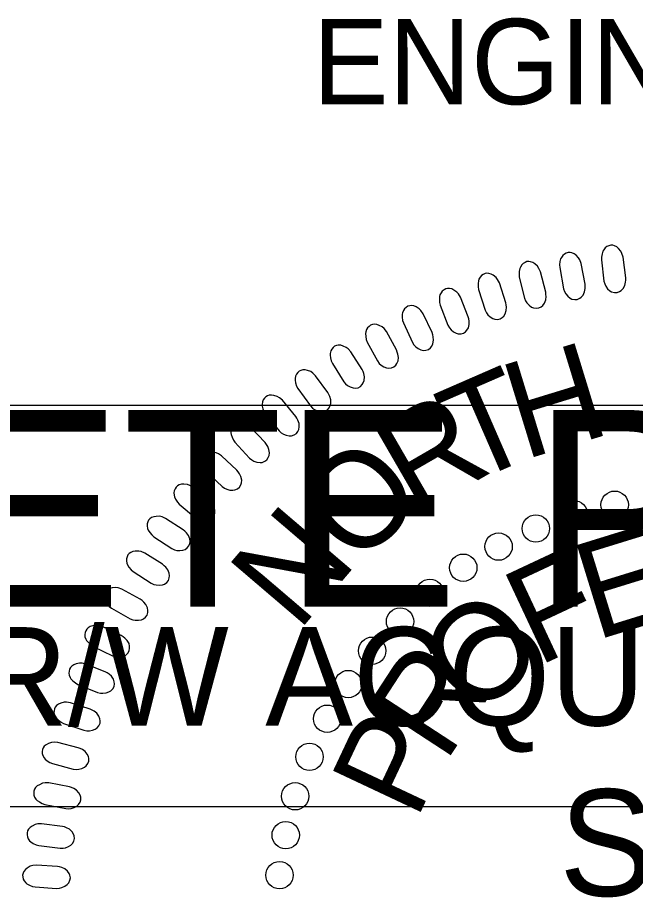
# Model space of a CAD drawing. Extents: x 505602 to 507286, y 483109 to 484209.
# Drawn here: x 507178.9 to 507215, y 484097.2 to 484148.7 of the extents above; entities that cross this region are included whole.
import ezdxf

# ---------------------------------------------------------------- set-up
doc = ezdxf.new("R2010")
doc.units = 0
for name, color, linetype in [('Sheet PE Seal Cell', 7, 'Continuous'), ('Sheet Profile CELL', 7, 'Continuous'), ('Sheet Sticker Incomplete CELL', 7, 'Continuous')]:
    doc.layers.add(name, color=color, linetype=linetype)

msp = doc.modelspace()

# ---------------------------------------------------------------- linework, layer by layer
at = {"layer": 'Sheet PE Seal Cell'}
for points in [[(507214.482, 484133.465), (507214.328, 484134.682), (507214.264, 484134.896), (507214.194, 484135.027), (507214.062, 484135.182), (507213.952, 484135.278), (507213.831, 484135.343), (507213.722, 484135.37), (507213.608, 484135.376), (507213.499, 484135.342), (507213.384, 484135.297), (507213.288, 484135.225), (507213.196, 484135.113), (507213.147, 484135.026), (507213.099, 484134.869), (507213.062, 484134.684), (507213.06, 484134.523), (507213.21, 484133.275), (507213.253, 484133.11), (507213.315, 484132.977), (507213.424, 484132.829), (507213.553, 484132.705), (507213.659, 484132.638), (507213.822, 484132.598), (507213.973, 484132.597), (507214.116, 484132.655), (507214.214, 484132.718), (507214.328, 484132.833), (507214.425, 484133.016), (507214.469, 484133.202), (507214.483, 484133.335)], [(507212.1, 484133.097), (507211.871, 484134.302), (507211.793, 484134.511), (507211.716, 484134.638), (507211.574, 484134.784), (507211.458, 484134.873), (507211.333, 484134.931), (507211.223, 484134.95), (507211.109, 484134.949), (507211.002, 484134.909), (507210.891, 484134.857), (507210.799, 484134.779), (507210.714, 484134.66), (507210.671, 484134.571), (507210.633, 484134.411), (507210.608, 484134.224), (507210.615, 484134.063), (507210.843, 484132.828), (507210.897, 484132.665), (507210.967, 484132.536), (507211.085, 484132.396), (507211.221, 484132.28), (507211.332, 484132.22), (507211.497, 484132.19), (507211.647, 484132.199), (507211.787, 484132.266), (507211.881, 484132.335), (507211.987, 484132.456), (507212.073, 484132.645), (507212.105, 484132.834), (507212.11, 484132.967)], [(507209.795, 484132.625), (507209.491, 484133.813), (507209.4, 484134.016), (507209.314, 484134.139), (507209.164, 484134.275), (507209.042, 484134.357), (507208.914, 484134.407), (507208.802, 484134.42), (507208.689, 484134.411), (507208.585, 484134.364), (507208.477, 484134.305), (507208.39, 484134.221), (507208.314, 484134.098), (507208.276, 484134.007), (507208.247, 484133.845), (507208.234, 484133.656), (507208.252, 484133.496), (507208.557, 484132.277), (507208.621, 484132.118), (507208.699, 484131.994), (507208.826, 484131.862), (507208.969, 484131.754), (507209.083, 484131.702), (507209.25, 484131.682), (507209.4, 484131.7), (507209.535, 484131.776), (507209.624, 484131.85), (507209.722, 484131.978), (507209.795, 484132.172), (507209.816, 484132.363), (507209.813, 484132.495)], [(507207.461, 484132.004), (507207.083, 484133.171), (507206.98, 484133.368), (507206.887, 484133.485), (507206.728, 484133.612), (507206.602, 484133.686), (507206.47, 484133.727), (507206.358, 484133.733), (507206.246, 484133.717), (507206.145, 484133.664), (507206.041, 484133.598), (507205.96, 484133.51), (507205.891, 484133.382), (507205.859, 484133.288), (507205.84, 484133.125), (507205.839, 484132.935), (507205.867, 484132.776), (507206.248, 484131.579), (507206.322, 484131.425), (507206.407, 484131.306), (507206.542, 484131.182), (507206.692, 484131.084), (507206.809, 484131.038), (507206.977, 484131.029), (507207.125, 484131.057), (507207.255, 484131.141), (507207.339, 484131.221), (507207.429, 484131.354), (507207.49, 484131.553), (507207.499, 484131.744), (507207.487, 484131.877)], [(507205.261, 484131.188), (507204.809, 484132.329), (507204.694, 484132.519), (507204.594, 484132.63), (507204.427, 484132.746), (507204.297, 484132.813), (507204.163, 484132.845), (507204.051, 484132.844), (507203.94, 484132.821), (507203.843, 484132.761), (507203.742, 484132.689), (507203.667, 484132.595), (507203.606, 484132.464), (507203.58, 484132.368), (507203.572, 484132.204), (507203.583, 484132.015), (507203.621, 484131.859), (507204.076, 484130.687), (507204.159, 484130.538), (507204.253, 484130.425), (507204.395, 484130.309), (507204.55, 484130.221), (507204.67, 484130.182), (507204.838, 484130.184), (507204.984, 484130.221), (507205.108, 484130.313), (507205.187, 484130.398), (507205.269, 484130.537), (507205.318, 484130.739), (507205.314, 484130.931), (507205.295, 484131.062)], [(507203.143, 484130.255), (507202.621, 484131.365), (507202.494, 484131.548), (507202.387, 484131.652), (507202.214, 484131.759), (507202.079, 484131.816), (507201.944, 484131.84), (507201.832, 484131.832), (507201.722, 484131.802), (507201.629, 484131.736), (507201.534, 484131.659), (507201.464, 484131.56), (507201.412, 484131.425), (507201.392, 484131.328), (507201.395, 484131.163), (507201.417, 484130.975), (507201.464, 484130.822), (507201.993, 484129.682), (507202.085, 484129.537), (507202.185, 484129.43), (507202.334, 484129.324), (507202.495, 484129.245), (507202.617, 484129.215), (507202.784, 484129.227), (507202.928, 484129.272), (507203.046, 484129.372), (507203.12, 484129.462), (507203.192, 484129.606), (507203.229, 484129.81), (507203.213, 484130.002), (507203.185, 484130.132)], [(507201.06, 484129.241), (507200.469, 484130.317), (507200.331, 484130.491), (507200.218, 484130.588), (507200.038, 484130.683), (507199.9, 484130.732), (507199.764, 484130.748), (507199.653, 484130.733), (507199.545, 484130.696), (507199.456, 484130.625), (507199.366, 484130.541), (507199.303, 484130.438), (507199.259, 484130.3), (507199.245, 484130.201), (507199.258, 484130.038), (507199.292, 484129.851), (507199.349, 484129.701), (507199.948, 484128.596), (507200.049, 484128.458), (507200.156, 484128.358), (507200.311, 484128.261), (507200.477, 484128.192), (507200.6, 484128.169), (507200.767, 484128.192), (507200.907, 484128.247), (507201.019, 484128.354), (507201.087, 484128.448), (507201.15, 484128.597), (507201.173, 484128.803), (507201.146, 484128.993), (507201.109, 484129.12)], [(507199.043, 484128.099), (507198.386, 484129.135), (507198.237, 484129.301), (507198.118, 484129.39), (507197.933, 484129.474), (507197.792, 484129.514), (507197.655, 484129.522), (507197.544, 484129.499), (507197.439, 484129.456), (507197.355, 484129.379), (507197.27, 484129.29), (507197.214, 484129.184), (507197.179, 484129.043), (507197.171, 484128.944), (507197.194, 484128.781), (507197.24, 484128.598), (507197.306, 484128.45), (507197.973, 484127.385), (507198.083, 484127.254), (507198.196, 484127.16), (507198.357, 484127.074), (507198.526, 484127.016), (507198.651, 484127), (507198.816, 484127.034), (507198.952, 484127.097), (507199.058, 484127.211), (507199.119, 484127.309), (507199.173, 484127.461), (507199.183, 484127.669), (507199.144, 484127.857), (507199.1, 484127.982)], [(507197.042, 484126.745), (507196.321, 484127.737), (507196.162, 484127.893), (507196.038, 484127.976), (507195.847, 484128.047), (507195.704, 484128.078), (507195.567, 484128.077), (507195.458, 484128.048), (507195.356, 484127.998), (507195.277, 484127.916), (507195.198, 484127.822), (507195.149, 484127.712), (507195.122, 484127.569), (507195.121, 484127.47), (507195.155, 484127.309), (507195.211, 484127.129), (507195.287, 484126.987), (507196.019, 484125.965), (507196.137, 484125.841), (507196.255, 484125.754), (507196.421, 484125.678), (507196.594, 484125.631), (507196.72, 484125.623), (507196.882, 484125.667), (507197.015, 484125.739), (507197.112, 484125.859), (507197.167, 484125.961), (507197.212, 484126.116), (507197.209, 484126.324), (507197.158, 484126.509), (507197.106, 484126.631)], [(507195.162, 484125.356), (507194.38, 484126.301), (507194.212, 484126.446), (507194.082, 484126.521), (507193.888, 484126.58), (507193.743, 484126.603), (507193.606, 484126.593), (507193.5, 484126.556), (507193.401, 484126.5), (507193.327, 484126.413), (507193.254, 484126.314), (507193.211, 484126.202), (507193.194, 484126.058), (507193.199, 484125.958), (507193.242, 484125.8), (507193.31, 484125.624), (507193.395, 484125.486), (507194.189, 484124.513), (507194.315, 484124.397), (507194.439, 484124.318), (507194.609, 484124.252), (507194.785, 484124.216), (507194.911, 484124.216), (507195.07, 484124.27), (507195.198, 484124.35), (507195.287, 484124.476), (507195.336, 484124.581), (507195.371, 484124.739), (507195.354, 484124.946), (507195.292, 484125.127), (507195.232, 484125.246)], [(507193.374, 484123.817), (507192.535, 484124.711), (507192.357, 484124.846), (507192.223, 484124.912), (507192.025, 484124.959), (507191.88, 484124.972), (507191.744, 484124.954), (507191.64, 484124.911), (507191.544, 484124.849), (507191.476, 484124.758), (507191.409, 484124.654), (507191.374, 484124.539), (507191.366, 484124.394), (507191.377, 484124.295), (507191.43, 484124.14), (507191.51, 484123.968), (507191.602, 484123.837), (507192.457, 484122.915), (507192.589, 484122.807), (507192.717, 484122.736), (507192.892, 484122.681), (507193.07, 484122.656), (507193.195, 484122.663), (507193.35, 484122.728), (507193.473, 484122.816), (507193.554, 484122.947), (507193.597, 484123.055), (507193.622, 484123.215), (507193.593, 484123.42), (507193.518, 484123.597), (507193.452, 484123.712)], [(507191.712, 484122.207), (507190.818, 484123.047), (507190.632, 484123.17), (507190.495, 484123.228), (507190.294, 484123.262), (507190.148, 484123.267), (507190.013, 484123.24), (507189.912, 484123.191), (507189.821, 484123.123), (507189.759, 484123.028), (507189.699, 484122.919), (507189.67, 484122.803), (507189.671, 484122.658), (507189.689, 484122.56), (507189.751, 484122.408), (507189.841, 484122.242), (507189.942, 484122.115), (507190.853, 484121.25), (507190.992, 484121.15), (507191.124, 484121.087), (507191.302, 484121.043), (507191.48, 484121.03), (507191.605, 484121.045), (507191.757, 484121.119), (507191.873, 484121.214), (507191.946, 484121.351), (507191.982, 484121.461), (507191.996, 484121.622), (507191.955, 484121.825), (507191.87, 484121.997), (507191.796, 484122.107)], [(507190.098, 484120.421), (507189.154, 484121.203), (507188.96, 484121.314), (507188.82, 484121.363), (507188.617, 484121.385), (507188.471, 484121.38), (507188.339, 484121.344), (507188.241, 484121.289), (507188.154, 484121.215), (507188.098, 484121.116), (507188.045, 484121.005), (507188.024, 484120.886), (507188.034, 484120.742), (507188.057, 484120.645), (507188.13, 484120.498), (507188.23, 484120.337), (507188.338, 484120.218), (507189.301, 484119.411), (507189.446, 484119.32), (507189.583, 484119.266), (507189.763, 484119.233), (507189.941, 484119.231), (507190.065, 484119.255), (507190.211, 484119.337), (507190.322, 484119.439), (507190.387, 484119.58), (507190.415, 484119.693), (507190.419, 484119.854), (507190.365, 484120.054), (507190.27, 484120.221), (507190.188, 484120.326)], [(507188.574, 484118.718), (507187.544, 484119.384), (507187.339, 484119.472), (507187.193, 484119.504), (507186.99, 484119.502), (507186.845, 484119.479), (507186.718, 484119.428), (507186.628, 484119.362), (507186.55, 484119.279), (507186.505, 484119.174), (507186.466, 484119.057), (507186.459, 484118.937), (507186.486, 484118.795), (507186.52, 484118.701), (507186.61, 484118.564), (507186.728, 484118.415), (507186.85, 484118.31), (507187.901, 484117.622), (507188.056, 484117.549), (507188.197, 484117.511), (507188.38, 484117.5), (507188.558, 484117.518), (507188.678, 484117.557), (507188.813, 484117.656), (507188.911, 484117.77), (507188.959, 484117.918), (507188.974, 484118.033), (507188.959, 484118.194), (507188.882, 484118.386), (507188.767, 484118.54), (507188.674, 484118.635)], [(507187.359, 484116.696), (507186.324, 484117.353), (507186.119, 484117.439), (507185.973, 484117.47), (507185.769, 484117.467), (507185.625, 484117.443), (507185.497, 484117.391), (507185.408, 484117.324), (507185.33, 484117.24), (507185.287, 484117.134), (507185.249, 484117.018), (507185.243, 484116.897), (507185.271, 484116.756), (507185.306, 484116.662), (507185.397, 484116.525), (507185.516, 484116.378), (507185.639, 484116.274), (507186.696, 484115.594), (507186.851, 484115.522), (507186.993, 484115.485), (507187.175, 484115.475), (507187.353, 484115.495), (507187.473, 484115.534), (507187.607, 484115.635), (507187.704, 484115.751), (507187.751, 484115.898), (507187.765, 484116.013), (507187.749, 484116.174), (507187.67, 484116.365), (507187.554, 484116.519), (507187.461, 484116.614)], [(507186.056, 484114.646), (507184.981, 484115.238), (507184.771, 484115.311), (507184.623, 484115.332), (507184.421, 484115.316), (507184.277, 484115.283), (507184.154, 484115.224), (507184.069, 484115.151), (507183.997, 484115.063), (507183.961, 484114.955), (507183.929, 484114.836), (507183.931, 484114.715), (507183.968, 484114.576), (507184.009, 484114.485), (507184.107, 484114.353), (507184.236, 484114.215), (507184.365, 484114.118), (507185.462, 484113.506), (507185.621, 484113.443), (507185.765, 484113.416), (507185.949, 484113.417), (507186.125, 484113.448), (507186.242, 484113.495), (507186.37, 484113.603), (507186.459, 484113.725), (507186.496, 484113.875), (507186.503, 484113.99), (507186.477, 484114.15), (507186.386, 484114.336), (507186.262, 484114.482), (507186.162, 484114.571)], [(507184.947, 484112.522), (507183.837, 484113.045), (507183.623, 484113.105), (507183.474, 484113.117), (507183.273, 484113.088), (507183.132, 484113.047), (507183.013, 484112.979), (507182.932, 484112.901), (507182.866, 484112.808), (507182.836, 484112.699), (507182.813, 484112.577), (507182.822, 484112.458), (507182.868, 484112.321), (507182.914, 484112.233), (507183.021, 484112.108), (507183.158, 484111.977), (507183.292, 484111.888), (507184.427, 484111.346), (507184.589, 484111.295), (507184.735, 484111.276), (507184.917, 484111.289), (507185.091, 484111.331), (507185.205, 484111.385), (507185.326, 484111.501), (507185.408, 484111.628), (507185.435, 484111.78), (507185.435, 484111.897), (507185.399, 484112.054), (507185.297, 484112.234), (507185.163, 484112.371), (507185.058, 484112.454)], [(507184.008, 484110.404), (507182.868, 484110.855), (507182.65, 484110.901), (507182.501, 484110.905), (507182.302, 484110.863), (507182.164, 484110.813), (507182.049, 484110.738), (507181.973, 484110.655), (507181.913, 484110.558), (507181.89, 484110.447), (507181.874, 484110.324), (507181.891, 484110.205), (507181.945, 484110.072), (507181.997, 484109.986), (507182.112, 484109.868), (507182.257, 484109.747), (507182.396, 484109.667), (507183.562, 484109.197), (507183.727, 484109.156), (507183.874, 484109.146), (507184.055, 484109.17), (507184.226, 484109.223), (507184.337, 484109.284), (507184.451, 484109.408), (507184.524, 484109.539), (507184.542, 484109.693), (507184.534, 484109.809), (507184.488, 484109.964), (507184.374, 484110.137), (507184.232, 484110.266), (507184.122, 484110.342)], [(507183.132, 484108.215), (507181.965, 484108.594), (507181.745, 484108.626), (507181.596, 484108.62), (507181.4, 484108.566), (507181.265, 484108.507), (507181.155, 484108.425), (507181.085, 484108.338), (507181.032, 484108.237), (507181.016, 484108.125), (507181.007, 484108.002), (507181.032, 484107.884), (507181.094, 484107.753), (507181.152, 484107.672), (507181.273, 484107.561), (507181.425, 484107.449), (507181.57, 484107.378), (507182.763, 484106.982), (507182.931, 484106.951), (507183.078, 484106.951), (507183.257, 484106.987), (507183.424, 484107.051), (507183.531, 484107.118), (507183.636, 484107.248), (507183.701, 484107.385), (507183.709, 484107.539), (507183.694, 484107.654), (507183.639, 484107.806), (507183.515, 484107.972), (507183.364, 484108.092), (507183.25, 484108.16)], [(507182.428, 484105.959), (507181.239, 484106.264), (507181.018, 484106.282), (507180.869, 484106.267), (507180.677, 484106.201), (507180.547, 484106.134), (507180.441, 484106.045), (507180.377, 484105.953), (507180.329, 484105.85), (507180.321, 484105.737), (507180.32, 484105.613), (507180.352, 484105.496), (507180.423, 484105.371), (507180.485, 484105.293), (507180.613, 484105.19), (507180.772, 484105.088), (507180.921, 484105.026), (507182.136, 484104.706), (507182.306, 484104.686), (507182.452, 484104.694), (507182.629, 484104.742), (507182.792, 484104.815), (507182.894, 484104.89), (507182.991, 484105.027), (507183.047, 484105.167), (507183.046, 484105.321), (507183.024, 484105.435), (507182.959, 484105.583), (507182.825, 484105.741), (507182.667, 484105.851), (507182.549, 484105.912)], [(507181.916, 484103.663), (507180.712, 484103.893), (507180.489, 484103.898), (507180.342, 484103.873), (507180.154, 484103.794), (507180.028, 484103.72), (507179.929, 484103.624), (507179.87, 484103.529), (507179.829, 484103.423), (507179.828, 484103.309), (507179.835, 484103.186), (507179.874, 484103.072), (507179.952, 484102.951), (507180.019, 484102.877), (507180.154, 484102.782), (507180.319, 484102.69), (507180.471, 484102.638), (507181.705, 484102.394), (507181.875, 484102.385), (507182.021, 484102.403), (507182.194, 484102.461), (507182.352, 484102.545), (507182.449, 484102.626), (507182.537, 484102.768), (507182.585, 484102.912), (507182.574, 484103.066), (507182.544, 484103.178), (507182.47, 484103.322), (507182.327, 484103.471), (507182.162, 484103.571), (507182.041, 484103.624)], [(507181.496, 484101.349), (507180.279, 484101.503), (507180.057, 484101.494), (507179.911, 484101.46), (507179.729, 484101.369), (507179.608, 484101.287), (507179.515, 484101.186), (507179.462, 484101.087), (507179.428, 484100.978), (507179.434, 484100.864), (507179.449, 484100.742), (507179.495, 484100.631), (507179.581, 484100.514), (507179.653, 484100.445), (507179.792, 484100.359), (507179.963, 484100.277), (507180.118, 484100.235), (507181.364, 484100.07), (507181.535, 484100.071), (507181.679, 484100.098), (507181.848, 484100.166), (507182.001, 484100.26), (507182.093, 484100.347), (507182.172, 484100.495), (507182.211, 484100.641), (507182.189, 484100.794), (507182.153, 484100.904), (507182.07, 484101.043), (507181.917, 484101.183), (507181.747, 484101.272), (507181.623, 484101.318)], [(507181.21, 484099.005), (507179.985, 484099.082), (507179.764, 484099.059), (507179.621, 484099.016), (507179.445, 484098.915), (507179.329, 484098.824), (507179.242, 484098.718), (507179.196, 484098.616), (507179.169, 484098.505), (507179.182, 484098.392), (507179.205, 484098.27), (507179.257, 484098.162), (507179.35, 484098.052), (507179.426, 484097.987), (507179.571, 484097.91), (507179.746, 484097.839), (507179.904, 484097.807), (507181.158, 484097.72), (507181.329, 484097.731), (507181.471, 484097.768), (507181.636, 484097.847), (507181.782, 484097.95), (507181.868, 484098.042), (507181.937, 484098.195), (507181.967, 484098.343), (507181.936, 484098.494), (507181.893, 484098.602), (507181.802, 484098.736), (507181.64, 484098.865), (507181.465, 484098.944), (507181.338, 484098.982)]]:
    msp.add_lwpolyline(points, close=True, dxfattribs=at)
for centre in [(507213.835, 484120.184), (507211.446, 484119.627), (507209.216, 484118.791), (507207.041, 484117.73), (507204.971, 484116.496), (507203.019, 484115.022), (507201.267, 484113.35), (507199.634, 484111.637), (507198.24, 484109.686), (507197.005, 484107.655), (507195.969, 484105.424), (507195.132, 484103.114), (507194.574, 484100.843), (507194.215, 484098.493)]:
    msp.add_circle(centre, 0.801, dxfattribs=at)
at = {"layer": 'Sheet Sticker Incomplete CELL'}
msp.add_lwpolyline([(507095.597, 484102.505), (507095.597, 484126.005), (507242.597, 484126.005), (507242.597, 484102.505)], close=True, dxfattribs=at)

# ---------------------------------------------------------------- texts
at = {"layer": 'Sheet PE Seal Cell'}
for s, height, rotation, p in [('H', 5.669, 17.0557, (507208.505, 484122.788)), ('T', 5.669, 23.5451, (507205.326, 484121.378)), ('R', 5.669, 30.0345, (507202.105, 484119.459)), ('O', 5.669, 43.0132, (507198.63, 484116.431)), ('N', 5.669, 49.5025, (507195.283, 484112.676)), ('E', 5.669, 17.1686, (507212.701, 484112.219)), ('F', 5.669, 25.1084, (507209.311, 484110.681)), ('O', 5.669, 40.988, (507205.614, 484107.542)), ('R', 5.669, 56.8676, (507203.9, 484104.996)), ('P', 5.669, 64.8074, (507202.214, 484101.634)), ('SEAL', 6.2363, 359.9814, (507210.585, 484097.285))]:
    msp.add_text(s, height=height, rotation=rotation, dxfattribs=at).set_placement(p)
at = {"layer": 'Sheet Profile CELL'}
msp.add_text('ENGINEER', height=5.0001, dxfattribs=at).set_placement((507196.142, 484143.624))
at = {"layer": 'Sheet Sticker Incomplete CELL'}
for s, height, p in [('INCOMPLETE PLANS', 11.52, (507104.547, 484114.205)), ('DO NOT USE FOR R/W ACQUISITION', 5.76, (507107.797, 484107.255))]:
    msp.add_text(s, height=height, dxfattribs=at).set_placement(p)

doc.saveas('drawing.dxf')
